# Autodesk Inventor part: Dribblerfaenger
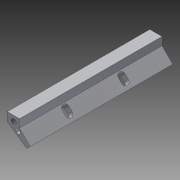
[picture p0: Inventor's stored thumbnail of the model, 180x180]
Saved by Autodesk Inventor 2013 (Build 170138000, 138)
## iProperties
Created: 2012-07
Part Number: Dribblerfaenger
Material: Aluminium 6061
Document SubType Name: Modeling
Designer: rYan
Mass: 8.23646 g
Surface Area: 25.295 cm^2
Volume: 3.03928 cm^3
Density: 2.71 g/cm^3
Author: rYan
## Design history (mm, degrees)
sketch "Skizze1"
  geometry: L1 (-3, -0.702)-(6, 5.6); L2 (0, -2.762)-(0, 11.66) reference; L3 (0.331, 5.867)-(-4.619, 0.917); L4 (-3, -0.702)-(-4.619, 0.917); L5 (-6.742, 0)-(8.124, 0) reference; L6 (0.331, 9.6)-(6, 9.6); L7 (6, 9.6)-(6, 5.6); L8 (0.331, 5.867)-(0.331, 9.6); 1 further point
  constraints: 12 end point, 2 parallel, 2 perpendicular
  dimensions: "d24" = 3.91421 distance from line of point (0, 0) L3; "d25" = 35 deg angle of L1 L5; "d26" = 45 deg angle of L3 L5; "d27" = 5.6 distance from line of L1.end L5; "d28" = 3 distance from line of L2 L1.start; "d41" = 6 distance between parallel lines of L2 L7; "d42" = 4 distance of L6.end L1.end; "d48" = 7 distance of L3.start L3.end
extrude "Extrusion1" new body sketch "Skizze1" distance "d2" = 66; taper "d3" = 0 deg
sketch "Skizze2"
  geometry: L1 (-7, 0)-(0, 0) reference; L2 (0, 0)-(0, 66) reference; L3 (-7, 66)-(0, 66) reference; L4 (0, 33)-(-10.866, 33); L5 (-3, 47.6)-(-5, 47.6); L6 (-5, 44.4)-(-3, 44.4); L7 (-5, 21.6)-(-3, 21.6); L8 (-3, 18.4)-(-5, 18.4); L9 (-7, 0)-(-7, 66) reference; A1 r 1.6 centre (-3, 46) between (-3, 44.4) and (-3, 47.6); A2 r 1.6 centre (-5, 46) between (-5, 47.6) and (-5, 44.4); A3 r 1.6 centre (-5, 20) between (-5, 21.6) and (-5, 18.4); A4 r 1.6 centre (-3, 20) between (-3, 18.4) and (-3, 21.6); 1 further point
  constraints: 10 end point, 8 point on circle, 8 tangent, 4 centre point, 2 horizontal, 2 parallel, 2 symmetric about line, 1 midpoint, 2 other
  dimensions: "d17" = 3.2 distance between parallel lines of L6 L5; "d19" = 26 distance of A3.centre A2.centre; "d20" = 2 distance of A2.centre A1.centre; "d21" = 3 distance from line of L2 A1.centre
extrude "Extrusion2" cut sketch "Skizze2" stored distance "d22" = 10; taper "d23" = 0 deg
sketch "Skizze3"
  geometry: L1 (-6, -9.6)-(-0.331, -9.6) reference; L2 (-6, -5.6)-(-6, -9.6) reference; C1 r 1 at (-8.892, -1.905); 3 further points
  constraints: 1 centre point
  dimensions: "d43" = 2.5 distance from line of L1 point (-3, -7.1); "d46" = 3 distance from line of L2 point (-3, -7.1); "d50" = 2 diameter of C1; "d51" = 2 horizontal distance of point (-1, -4.1) point (-3, -7.1); "d52" = 3 vertical distance of point (-1, -4.1) point (-3, -7.1)
hole "Bohrung1" sketch "Skizze3" at (-3, -7.1) diameter "d34" = 2.459; stored, may be unused: countersink angle "d38" = 90 deg, drill point angle "d40" = 118 deg; dims "d35" = 8, "d36" = 4, "d37" = 2, "d39" = 8
sketch "Skizze4"
  geometry: L1 (-6, -5.6)-(-6, -9.6) reference; L2 (-6, -9.6)-(-0.331, -9.6) reference; 2 further points
  dimensions: "d53" = 5 distance from line of point (-1, -4.1) L1; "d54" = 5.5 distance from line of L2 point (-1, -4.1)
hole "Bohrung2" sketch "Skizze4" at (-1, -4.1) diameter "d55" = 2; stored, may be unused: countersink angle "d59" = 90 deg, drill point angle "d61" = 118 deg; dims "d56" = 6, "d57" = 4, "d58" = 2, "d60" = 3
workplane "Arbeitsebene1"
mirror "Spiegeln1"
node "Volumenkörper1"
node "Projizierte Kontur1"
